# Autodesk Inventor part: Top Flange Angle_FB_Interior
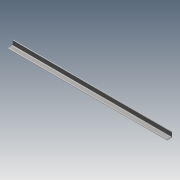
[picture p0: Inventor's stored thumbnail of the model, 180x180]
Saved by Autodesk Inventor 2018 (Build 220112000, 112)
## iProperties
Created: 2018-02
Part Number: Top Flange Angle_FB_Interior
Material: Steel, Mild
Document SubType Name: Modeling
Designer: STK
Mass: 216503 g
Surface Area: 46063.6 cm^2
Volume: 27580 cm^3
Density: 7.85 g/cm^3
Appearance: Semi-Polished
Author: STK
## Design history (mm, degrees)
derived "Top Flange Angle_FB_End.ipt"
feature "Solid1::Top Flange Angle_FB_End.ipt"
tag "TaggingFeature1"
body "Solid1"
